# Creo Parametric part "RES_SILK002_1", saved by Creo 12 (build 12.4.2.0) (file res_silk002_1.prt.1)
Units: Custom; MM, KILOGRAM, SECS

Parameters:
  PTC_WM_ITERATION = "0"
  PTC_WM_VERSION = "-.0"
  PTC_WM_LIFECYCLE_STATE = "In Work"
  PTC_WM_LIFECYCLE = "MO_CADDocument"
  PTC_WM_CREATED_BY = "Maximilian Roepper (Z0017RMS: MO)"
  PTC_WM_CREATED_ON = "18-Sep-26 11:36:42 AM"
  PTC_WM_MODIFIED_BY = "Maximilian Roepper (Z0017RMS: MO)"
  PTC_WM_MODIFIED_ON = "18-Sep-26 11:36:46 AM"
  PDMLINKNUMBER = "PDM000071455191"
  PTC_WM_NAME = "res_silk002_1.prt"
  PTC_WM_NUMBER = "PDM000071455191"

Other parameters: WEIGHT, WEIGHT_FACTOR, WEIGHT_ADD, _MASS_TEMP, _DIFF_TEMP, MC_ERRORS, SUPPLIER

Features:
  1. coordinate system
  2. datum plane "PRT_YZ"
  3. datum plane "PRT_XY"
  4. datum plane "PRT_XZ"
  5. coordinate system
  6. datum axis
  7. datum axis
  8. datum axis
  9. coordinate system
  10. imported feature

Other named items: PRT, SIEMENS_MO, DRW_VIEW_ORG, PRT_X, PRT_Y, PRT_Z, CS0, ROUGH_GROB

Layers: 00_STD_CSYS-KSYS, 01_STD_PLANES-EBENEN, 02_STD_AXES-ACHSEN, 03_STD_CSYS-KSYS, 24_IMPORT_FEAT-IMPORT_KE

Surfaces: 10 plane, 8 cylinder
